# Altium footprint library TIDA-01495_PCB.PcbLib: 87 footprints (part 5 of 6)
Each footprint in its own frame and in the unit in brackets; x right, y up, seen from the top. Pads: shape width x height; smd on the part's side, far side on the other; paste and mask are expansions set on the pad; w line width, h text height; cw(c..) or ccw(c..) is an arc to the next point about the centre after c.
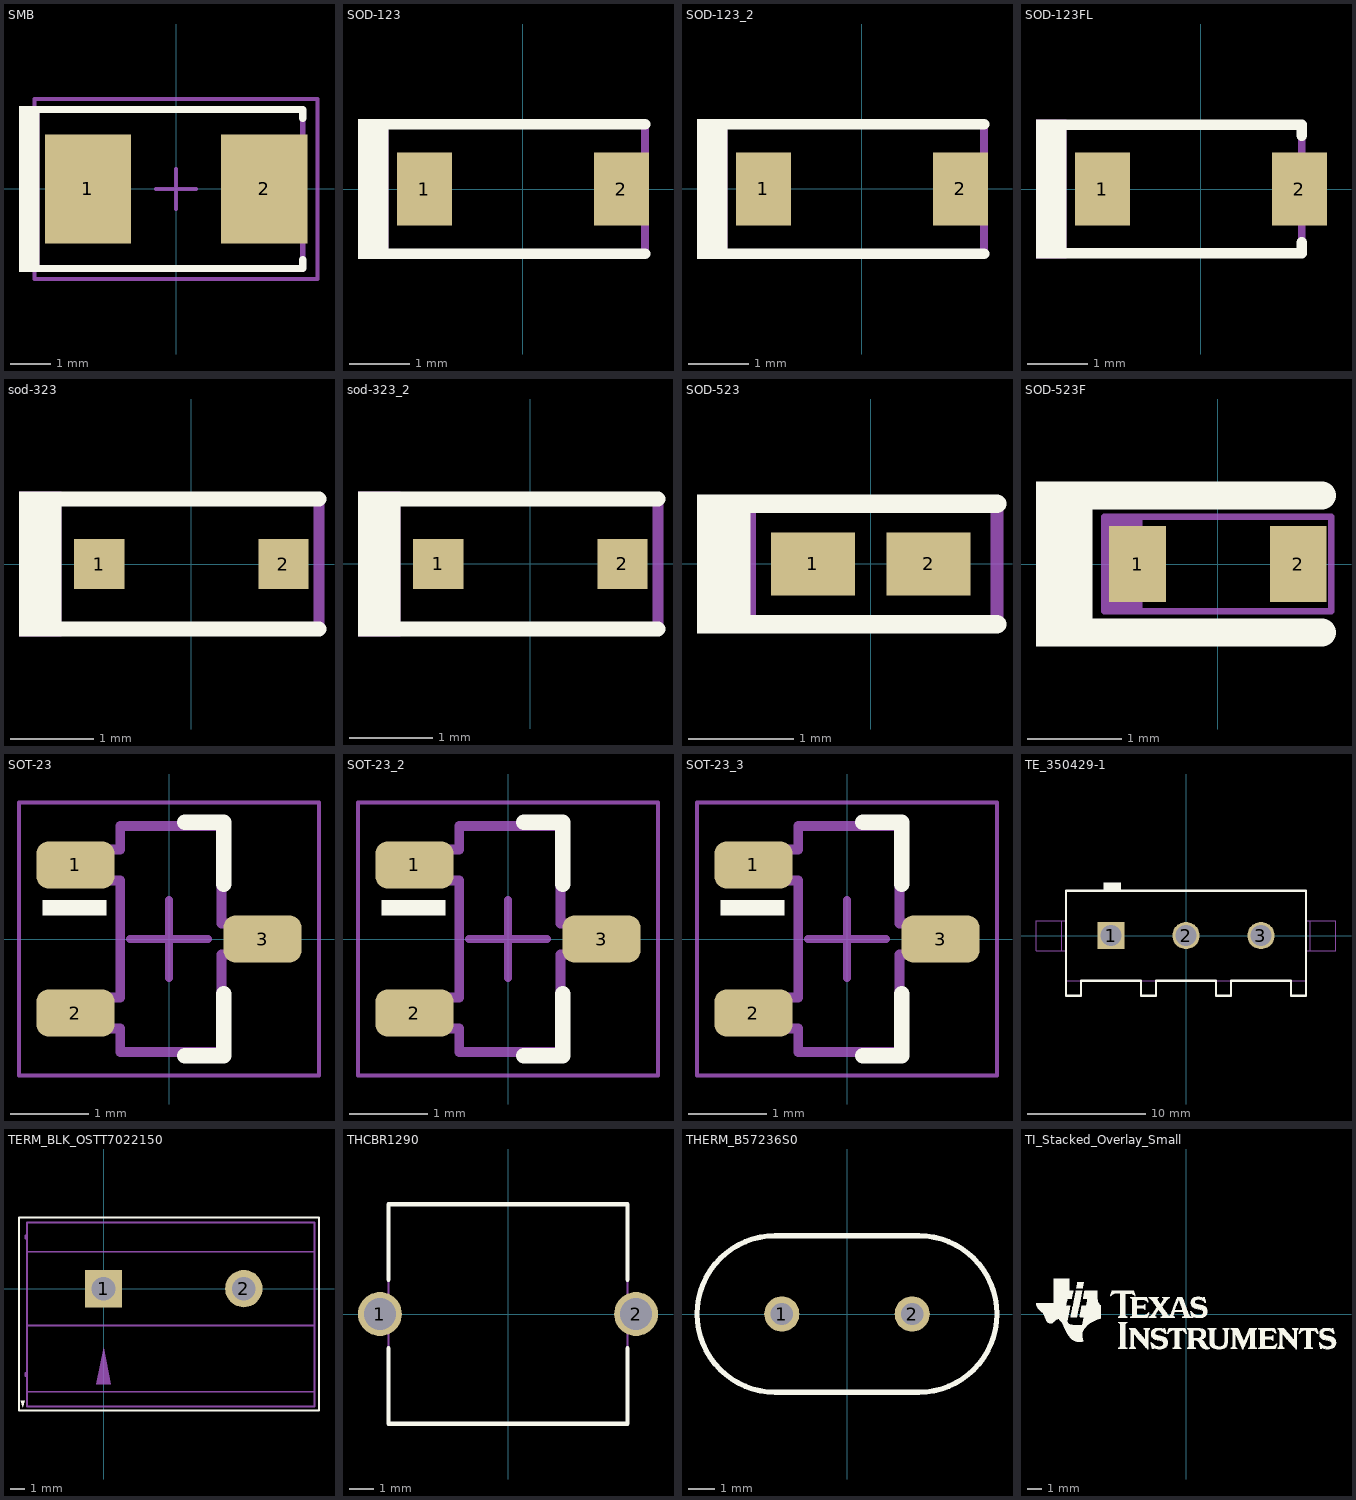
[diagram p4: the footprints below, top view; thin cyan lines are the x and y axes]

## SMB [mm] "Molded Diode, 2-Leads, Body 5.4x3.6mm, IPC Medium Density, based on OnSemi component dimensions"
height 2.65
pads (2):
  rect 2.159x2.743 smd: 1(-2.21,0) 2(2.21,0)
Top Overlay:
  rectangle: -3.937,-2.083 -3.429,2.083
  lines w0.178: -3.607,-1.994 3.175,-1.994 3.175,-1.765 ; -3.607,1.994 3.175,1.994 3.175,1.765
Mechanical 5:
  rectangle: -3.937,-2.083 -3.429,2.083
  lines w0.127: -3.607,-1.994 3.175,-1.994 3.175,-1.765 3.175,1.765 3.175,1.994 -3.607,1.994
  text ".Designator" at -1.465,-0.503 h1.02
Mechanical 15:
  lines w0.1: -0.5,0 0.5,0 ; 0,-0.5 0,0.5 ; -3.55,-2.25 -3.55,2.25 3.55,2.25 3.55,-2.25 -3.55,-2.25
3D body "SMB_nominal.stp": height 2.32, standoff 0.02, extent -2.7,-1.8 2.7,1.8

## SOD-123 [mm] "On Semi recommended land pattern"
height 1.35
pads (2):
  rect 0.915x1.22 smd: 1(-1.637,0) 2(1.637,0)
Top Overlay:
  rectangle: -2.744,-1.168 -2.236,1.169
  lines w0.178: -2.413,-1.079 2.032,-1.079 ; -2.413,1.079 2.032,1.079
Mechanical 5:
  rectangle: -2.744,-1.168 -2.236,1.169
  lines w0.127: -2.413,-1.079 2.032,-1.079 2.032,1.079 -2.413,1.079
  text ".Designator" at 0.55,0.476 h0.89
3D body "SOD-123.stp": height 1.35, standoff 0, extent -1.932,-0.9 1.932,0.9

## SOD-123_2 [mm]
pads (2):
  rect 0.915x1.22 smd: 1(-1.637,0) 2(1.637,0)
Top Overlay:
  rectangle: -2.744,-1.168 -2.236,1.168
  lines w0.178: -2.413,-1.079 2.032,-1.079 ; -2.413,1.079 2.032,1.079
Mechanical 5:
  rectangle: -2.744,-1.168 -2.236,1.168
  lines w0.127: -2.413,-1.079 2.032,-1.079 2.032,1.079 -2.413,1.079
  text ".Designator" at -1.073,-0.418 h0.76
3D body "SOD-123.stp": height 1.35, standoff 0, extent -1.932,-0.9 1.932,0.9

## SOD-123FL [mm] "Copied from SOD-123"
height 0.991
pads (2):
  rect 0.915x1.22 smd: 1(-1.637,0) 2(1.637,0)
Top Overlay:
  rectangle: -2.743,-1.156 -2.235,1.156
  lines w0.178: -2.438,-1.067 1.676,-1.067 1.676,-0.889 ; -2.438,1.067 1.676,1.067 1.676,0.889
Mechanical 5:
  rectangle: -2.743,-1.156 -2.235,1.156
  lines w0.127: -2.438,-1.067 1.676,-1.067 1.676,1.067 -2.438,1.067
  text ".Designator" at -1.93,-0.229 h0.76
3D body "SOD-123FL.stp": height 1, standoff 0, extent -1.9,-0.9 1.9,0.9

## sod-323 [mm] "NXP recommended land pattern"
height 1.15
pads (2):
  rect 0.6x0.6 smd paste-0.05: 1(-1.1,0) 2(1.1,0)
Top Overlay:
  rectangle: -2.057,-0.864 -1.549,0.864
  lines w0.178: -1.803,-0.775 0.1,-0.775 1.525,-0.775 ; -1.803,0.775 0.1,0.775 1.525,0.775
Mechanical 5:
  rectangle: -2.057,-0.864 -1.549,0.864
  lines w0.127: -1.803,-0.775 0.1,-0.775 1.525,-0.775 1.525,0.775 0.1,0.775 -1.803,0.775
  text ".Designator" at -0.81,-0.462 h0.76
3D body "SOD-323.stp": height 1.1, standoff 0, extent -1.3,-0.675 1.3,0.675

## sod-323_2 [mm]
pads (2):
  rect 0.6x0.6 smd paste-0.05: 1(-1.1,0) 2(1.1,0)
Top Overlay:
  rectangle: -2.057,-0.864 -1.549,0.864
  lines w0.178: -1.803,-0.775 0.1,-0.775 1.525,-0.775 ; -1.803,0.775 0.1,0.775 1.525,0.775
Mechanical 5:
  rectangle: -2.057,-0.864 -1.549,0.864
  lines w0.127: -1.803,-0.775 0.1,-0.775 1.525,-0.775 1.525,0.775 0.1,0.775 -1.803,0.775
  text ".Designator" at -1.06,-0.343 h0.76
3D body "SOD-323.stp": height 1.1, standoff 0, extent -1.3,-0.675 1.3,0.675

## SOD-523 [mm] "NXP Semiconductor recommended land pattern, nominal STEP model"
height 0.7
pads (2):
  rect 0.8x0.6 smd paste-0.05: 1(-0.55,0) 2(0.55,0)
Top Overlay:
  rectangle: -1.651,-0.66 -1.143,0.66
  lines w0.178: -1.475,-0.572 0,-0.572 1.2,-0.572 ; -1.475,0.572 0,0.572 1.2,0.572
Mechanical 5:
  rectangle: -1.6,-0.635 -1.092,0.635
  lines w0.127: -1.475,-0.546 0,-0.546 1.2,-0.546 1.2,0.546 0,0.559 -1.475,0.559
  text ".Designator" at -0.991,-0.279 h0.56
3D body "SOD-523F.stp": height 0.72, standoff 0.02, extent -0.8,-0.399 0.8,0.399

## SOD-523F [mm] "COMCHIP"
height 0.85
pads (2):
  rect 0.6x0.8 smd paste-0.05: 1(-0.85,0) 2(0.85,0)
Top Overlay:
  rectangle: -1.925,-0.875 -1.325,0.875
  lines w0.3: -1.5,-0.725 1.1,-0.725 ; -1.5,0.725 1.1,0.725
Mechanical 5:
  rectangle: -1.2,-0.5 -0.8,0.5
  lines w0.07: -1.2,-0.5 -1.2,0.5 1.2,0.5 1.2,-0.5 -1.2,-0.5
  text ".Designator" at -0.675,-0.275 h0.46
3D body: height 0.85, standoff 0.84, extent -0.899,-0.499 -0.401,0.499
3D body: height 0.85, standoff 0, extent -0.899,-0.499 0.899,0.499

## SOT-23 [mm] "SOT23, 3-Leads, Body 2.9x1.3mm, Pitch 0.95mm, Lead Span 2.5mm, IPC Medium Density"
height 1.1
pads (3):
  rrect50% 1x0.6 smd: 1(-1.2,0.95) 2(-1.2,-0.95) 3(1.2,0)
Top Overlay:
  rectangle: -1.625,0.3 -0.8,0.5
  lines w0.2: 0.2,-1.5 0.7,-1.5 0.7,-0.7 ; 0.2,1.5 0.7,1.5 0.7,0.7
Mechanical 5:
  lines w0.127: -1.16,-1.15 -1.16,-0.75 -0.625,-0.75 -0.625,0.75 -1.16,0.75 -1.16,1.15 -0.625,1.15 -0.625,1.45 0.675,1.45 0.675,0.2 1.21,0.2 1.21,-0.2 0.675,-0.2 0.675,-1.45 -0.625,-1.45 -0.625,-1.15 -1.16,-1.15
  text ".Designator" at -0.175,1.225 h0.64
Mechanical 15:
  lines w0.05: -1.925,-1.75 1.925,-1.75 1.925,1.75 -1.925,1.75 -1.925,-1.75
  lines w0.1: -0.5,0 0.5,0 ; 0,-0.5 0,0.5
3D body "SW3dPS-sot-3p290x130ll237h100.STEP": height 1, standoff 0, extent -1.16,-1.45 1.21,1.45

## SOT-23_2 [mm]
pads (3):
  rrect50% 1x0.6 smd: 1(-1.2,0.95) 2(-1.2,-0.95) 3(1.2,0)
Top Overlay:
  rectangle: -1.625,0.3 -0.8,0.5
  lines w0.2: 0.2,-1.5 0.7,-1.5 0.7,-0.7 ; 0.2,1.5 0.7,1.5 0.7,0.7
Mechanical 5:
  lines w0.127: -1.16,-1.15 -0.625,-1.15 -0.625,-1.45 0.675,-1.45 0.675,-0.2 1.21,-0.2 1.21,0.2 0.675,0.2 0.675,1.45 -0.625,1.45 -0.625,1.15 -1.16,1.15 -1.16,0.75 -0.625,0.75 -0.625,-0.75 -1.16,-0.75 -1.16,-1.15
  text ".Designator" at -0.443,1.011 h0.89
Mechanical 15:
  lines w0.05: -1.925,-1.75 -1.925,1.75 1.925,1.75 1.925,-1.75 -1.925,-1.75
  lines w0.1: -0.5,0 0.5,0 ; 0,-0.5 0,0.5
3D body "SW3dPS-sot-3p290x130ll237h100.STEP": height 1, standoff 0, extent -1.16,-1.45 1.21,1.45

## SOT-23_3 [mm]
pads (3):
  rrect50% 1x0.6 smd: 1(-1.2,0.95) 2(-1.2,-0.95) 3(1.2,0)
Top Overlay:
  rectangle: -1.625,0.3 -0.8,0.5
  lines w0.2: 0.2,-1.5 0.7,-1.5 0.7,-0.7 ; 0.2,1.5 0.7,1.5 0.7,0.7
Mechanical 5:
  lines w0.127: -1.16,-1.15 -0.625,-1.15 -0.625,-1.45 0.675,-1.45 0.675,-0.2 1.21,-0.2 1.21,0.2 0.675,0.2 0.675,1.45 -0.625,1.45 -0.625,1.15 -1.16,1.15 -1.16,0.75 -0.625,0.75 -0.625,-0.75 -1.16,-0.75 -1.16,-1.15
  text ".Designator" at -0.422,0.662 h0.89
Mechanical 15:
  lines w0.05: -1.925,-1.75 -1.925,1.75 1.925,1.75 1.925,-1.75 -1.925,-1.75
  lines w0.1: -0.5,0 0.5,0 ; 0,-0.5 0,0.5
3D body "SW3dPS-sot-3p290x130ll237h100.STEP": height 1, standoff 0, extent -1.16,-1.45 1.21,1.45

## TE_350429-1 [mm] "Header(Shrouded), 6.35mm, 3x1, TH"
height 14.99
pads (3):
  rect 2.3x2.3 hole 1.78: 1(-6.35,0)
  round 2.3 hole 1.78: 2(0,0) 3(6.35,0)
Top Overlay:
  rectangle: -7,3.81 -5.5,4.5
  lines w0.2: -10.16,-5.08 -10.16,3.81 10.16,3.81 10.16,-5.08 8.89,-5.08 8.89,-3.81 3.81,-3.81 3.81,-5.08 2.54,-5.08 2.54,-3.81 -2.54,-3.81 -2.54,-5.08 -3.81,-5.08 -3.81,-3.81 -8.89,-3.81 -8.89,-5.08 -10.16,-5.08
Mechanical 5:
  lines w0.1: -8.89,-3.81 -8.89,-5.08 -10.16,-5.08 -10.16,-3.81 ; -3.81,-3.81 -3.81,-5.08 -2.54,-5.08 -2.54,-3.81 ; 2.54,-3.81 2.54,-5.08 3.81,-5.08 3.81,-3.81 ; 8.89,-3.81 8.89,-5.08 10.16,-5.08 10.16,-3.81 ; -10.5,-1.27 -10.16,-1.27 -10.16,-3.81 ; -10.5,-1.27 -10.5,1.27 ; -10.5,-1.27 -12.7,-1.27 -12.7,1.27 -10.5,1.27 ; -10.5,1.27 -10.16,1.27 -10.16,3.81 10.16,3.81 10.16,1.27 10.5,1.27 ; -10.16,-3.81 10.16,-3.81 ; 10.16,-3.81 10.16,-1.27 10.5,-1.27 ; 10.5,-1.27 12.7,-1.27 12.7,1.27 10.5,1.27 ; 10.5,-1.27 10.5,1.27
  text ".Designator" at 1.209,0.507 h1.02
3D body "350429-1.stp": height 14.83, standoff -3.54, extent -12.7,-5.08 12.7,3.81

## TERM_BLK_OSTT7022150 [mm]
height 21.5
pads (2):
  rect 2.54x2.54 hole 1.6: 1(0,0)
  round 2.54 hole 1.6: 2(9.525,0)
Top Overlay:
  region: -5.483,-8.048 -5.33,-7.616 -5.61,-7.616
  lines w0.152: -5.737,-8.276 14.63,-8.276 14.63,4.83 -5.737,4.83 -5.737,3.941 -5.737,3.103 -5.737,-5.381 -5.737,-6.219 -5.737,-8.276
Mechanical 5:
  circle w0.127: c0,0 r0.4
  circle w0.127: c9.52,0 r0.4
  region: -0.5,-6.5 0,-4 0.5,-6.5
  lines w0.127: -5.2,-7 14.325,-7 ; -5.2,-5.925 -5.3,-5.925 -5.3,-5.725 -5.2,-5.725 ; -5.2,-2.5 14.325,-2.5 ; -5.2,2.5 14.325,2.5 ; -5.2,3.4 -5.3,3.4 -5.3,3.6 -5.2,3.6 ; -5.2,-8 14.325,-8 14.325,4.5 -5.2,4.5 -5.2,-8
  text ".Designator" at 3.962,0.979 h0.89
3D body: height 0, standoff -4.2, extent 9.024,-0.499 10.02,0.499
3D body: height 0, standoff -4.2, extent -0.496,-0.499 0.5,0.499
3D body: height 11, standoff 0, extent -5.3,3.4 -5.2,3.6
3D body: height 12, standoff 0, extent -5.3,-5.925 -5.2,-5.725
3D body: height 21.5, standoff 0, extent -5.2,-2.5 14.325,2.5
3D body: height 11, standoff 0, extent -5.451,3.352 14.074,5.352
3D body: height 12, standoff 10, extent -5.2,-8 14.325,-2.5
3D body: height 21.6, standoff 1.6, extent -2.232,-2.245 2.25,2.246
3D body: height 21.6, standoff 1.6, extent 7.293,-2.245 11.775,2.246
3D body: height 2, standoff 0, extent -5.195,-8 14.325,-2.5
3D body: height 12, standoff 0, extent -5.2,-8 -2.6,-2.5
3D body: height 12, standoff 0, extent 2.6,-8 4.76,-2.5
3D body: height 12, standoff 0, extent 4.509,-7.148 6.669,-1.648
3D body: height 12, standoff 0, extent 11.874,-7.148 14.074,-1.648

## THCBR1290 [mm] "Delta Electronics"
height 9.2
pads (2):
  round 1.8 hole 1.3: 1(-5.25,0) 2(5.25,0)
Top Overlay:
  lines w0.178: -4.9,-1.4 -4.9,-4.5 4.9,-4.5 4.9,-1.4 ; -4.9,1.4 -4.9,4.5 4.9,4.5 4.9,1.4
Mechanical 5:
  lines w0.1: -4.9,-4.5 -4.9,4.5 4.9,4.5 4.9,-4.5 -4.9,-4.5
  text ".Designator" at -1.123,-0.316 h0.89
3D body: height 9.2, standoff 0, extent -4.899,-4.499 4.899,4.499

## THERM_B57236S0 [mm] "EPCOS"
height 16
pads (2):
  round 1.35 hole 0.85: 1(-2.5,0) 2(2.5,0)
Top Overlay:
  lines w0.2: -2.75,-3 cw(c-2.75,0) -2.75,3 2.75,3 cw(c2.75,0) 2.75,-3 -2.75,-3
Mechanical 5:
  lines w0.1: -2.75,-3 cw(c-2.75,0) -2.75,3 2.75,3 cw(c2.75,0) 2.75,-3 -2.75,-3
  text ".Designator" at -0.439,1.22 h1.02
3D body: height 5.5, standoff -2.5, extent -2.797,-0.299 -2.2,0.3
3D body: height 5.5, standoff -2.5, extent 2.202,-0.299 2.8,0.3
3D body: height 15.99, standoff 4.51, extent -5.755,-3 5.7,3

## TI_Stacked_Overlay_Small [mm]
Top Overlay:
  drawing of 18 lines, arcs and shapes, not listed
